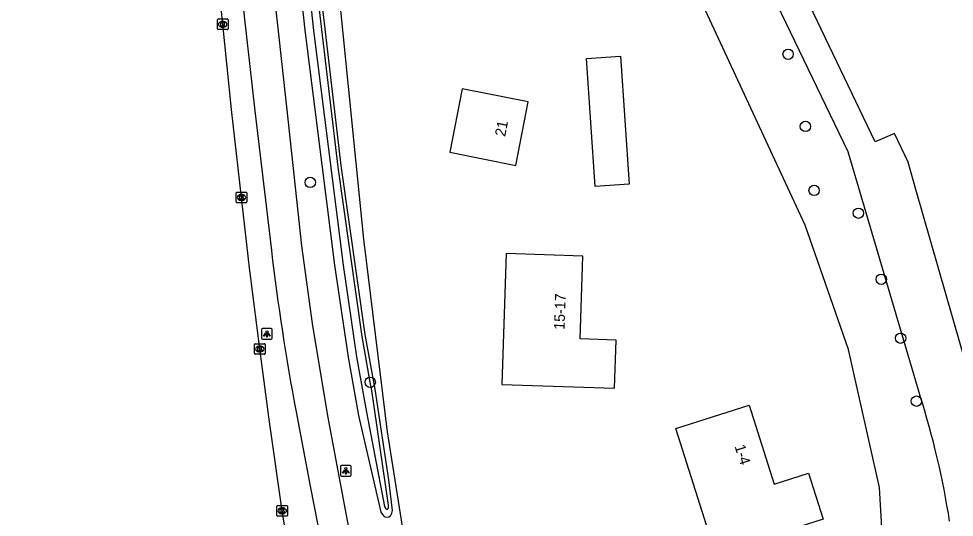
# Model space of a CAD drawing. Extents: x 159451 to 160663, y 388402 to 389723.
# Drawn here: x 159455.9 to 159544.3, y 389152.9 to 389199.9 of the extents above; entities that cross this region are included whole.
import ezdxf

# ---------------------------------------------------------------- set-up
doc = ezdxf.new("R2010")
doc.units = 0
for name, color, linetype in [('IMGEO_Boom', 7, 'Continuous'), ('IMGEO_Bouwland', 7, 'Continuous'), ('IMGEO_Fietspad_gesloten', 7, 'Continuous'), ('IMGEO_Grasland_overig', 7, 'Continuous'), ('IMGEO_Greppel_droge_sloot', 7, 'Continuous'), ('IMGEO_Groenvoorziening', 7, 'Continuous'), ('IMGEO_Kolk', 7, 'Continuous'), ('IMGEO_Lichtpunt', 7, 'Continuous'), ('IMGEO_Pand', 7, 'Continuous'), ('IMGEO_Pand_nummerreeks', 7, 'Continuous'), ('IMGEO_Pand_vergunning_verleend', 7, 'Continuous'), ('IMGEO_Rijbaan_regionaal_gesloten', 7, 'Continuous')]:
    doc.layers.add(name, color=color, linetype=linetype)

msp = doc.modelspace()

# ---------------------------------------------------------------- linework, layer by layer
at = {"layer": 'IMGEO_Boom'}
for centre in [(159528.616, 389196.58), (159530.24, 389189.771), (159483.48, 389184.488), (159531.071, 389183.726), (159535.251, 389181.578), (159537.411, 389175.343), (159539.233, 389169.779), (159489.139, 389165.616), (159540.731, 389163.833)]:
    msp.add_circle(centre, 0.489, dxfattribs=at)
at = {"layer": 'IMGEO_Bouwland'}
for points in [[(159495.943, 389125.547), (159492.959, 389147.253), (159490.78, 389160.929), (159488.551, 389179.124), (159479.211, 389271.897), (159478.228, 389288.738), (159480.836, 389288.81), (159487.441, 389272.575)], [(159539.156, 389122.203), (159538.081, 389141.023), (159537.243, 389155.693), (159534.303, 389168.702), (159530.224, 389180.456), (159487.441, 389272.575)]]:
    msp.add_lwpolyline(points, dxfattribs=at)
at = {"layer": 'IMGEO_Fietspad_gesloten'}
for points in [[(159455.942, 389525.002), (159456.038, 389522.126), (159456.372, 389512.313), (159456.916, 389496.35), (159457.955, 389465.071), (159459.294, 389436.93), (159461.071, 389403.687), (159462.508, 389376.402), (159464.342, 389348.5), (159465.649, 389329.916), (159467.063, 389310.472), (159468.609, 389291.384), (159470.151, 389272.51), (159471.683, 389255.143), (159473.293, 389238.955), (159476.115, 389210.723), (159476.688, 389204.954), (159478.244, 389191.231), (159479.81, 389178.066)], [(159492.482, 389125.078), (159491.057, 389131.504), (159487.963, 389147.366), (159485.138, 389162.462), (159483.697, 389171.161), (159482.691, 389178.486), (159481.255, 389191.613), (159479.595, 389206.774), (159479.167, 389211.269), (159476.315, 389239.166), (159474.73, 389255.582), (159473.199, 389272.868), (159471.882, 389288.893)], [(159482.145, 389162.815), (159483.459, 389155.81), (159485.311, 389146.532), (159487.529, 389135.114), (159489.673, 389123.332)]]:
    msp.add_lwpolyline(points, dxfattribs=at)
msp.add_arc((159698.001, 389203.668), 219.688, 186.6923, 190.71702, dxfattribs=at)
at = {"layer": 'IMGEO_Grasland_overig'}
for points in [[(159552.375, 389144.269), (159550.196, 389160.656), (159546.355, 389164.126), (159540.689, 389183.824), (159539.945, 389186.409), (159538.67, 389189.107), (159536.847, 389188.304), (159486.712, 389292.863)], [(159493.1, 389273.212), (159500, 389258.58), (159504.093, 389250), (159534.245, 389187.399), (159541.062, 389164.374)]]:
    msp.add_lwpolyline(points, dxfattribs=at)
msp.add_arc((159465.827, 389140.335), 78.982, 8.85455, 17.72, dxfattribs=at)
at = {"layer": 'IMGEO_Greppel_droge_sloot'}
msp.add_lwpolyline([(159481.882, 389216.377), (159483.778, 389198.834), (159486.574, 389176.685), (159487.854, 389168.014), (159488.602, 389163.826), (159488.797, 389162.797), (159490.487, 389153.895), (159490.538, 389153.785), (159490.596, 389153.695), (159490.701, 389153.64), (159490.759, 389153.652), (159490.843, 389153.709), (159490.882, 389153.795), (159490.884, 389153.895), (159490.866, 389154.004), (159489.544, 389163.12), (159489.298, 389164.837), (159489.139, 389165.616), (159488.368, 389169.95), (159486.114, 389185.938), (159483.986, 389203.971)], dxfattribs=at)
at = {"layer": 'IMGEO_Groenvoorziening'}
msp.add_lwpolyline([(159474.893, 389291.192), (159478.151, 389250), (159479.346, 389234.239), (159481.073, 389216.395), (159482.97, 389198.843), (159485.767, 389176.684), (159487.05, 389167.999), (159488.037, 389162.469), (159490.153, 389153.348), (159490.295, 389153.124), (159490.458, 389152.949), (159490.624, 389152.875), (159490.9, 389152.917), (159491.057, 389153.021), (159491.194, 389153.27), (159491.245, 389153.512), (159490.896, 389156.395), (159489.602, 389164.953), (159488.663, 389170.113), (159486.412, 389186.084), (159484.285, 389204.106), (159480.958, 389236.812), (159479.998, 389250), (159476.978, 389291.487)], dxfattribs=at)
at = {"layer": 'IMGEO_Kolk'}
for p, q in [((159474.712, 389198.983), (159474.712, 389199.835)), ((159474.787, 389199.909), (159475.639, 389199.909)), ((159475.2, 389199.689), (159475.225, 389199.689)), ((159475.713, 389199.835), (159475.713, 389198.983)), ((159475.639, 389198.909), (159474.787, 389198.909)), ((159475.223, 389199.129), (159475.198, 389199.129)), ((159476.555, 389183.562), (159477.407, 389183.562)), ((159476.48, 389182.636), (159476.48, 389183.488)), ((159476.991, 389182.782), (159476.966, 389182.782)), ((159476.968, 389183.342), (159476.993, 389183.342)), ((159477.481, 389183.488), (159477.481, 389182.636)), ((159477.407, 389182.562), (159476.555, 389182.562)), ((159478.212, 389168.333), (159478.212, 389169.185)), ((159478.287, 389169.259), (159479.139, 389169.259)), ((159478.7, 389169.039), (159478.725, 389169.039)), ((159479.213, 389169.185), (159479.213, 389168.333)), ((159479.139, 389168.259), (159478.287, 389168.259)), ((159478.723, 389168.479), (159478.698, 389168.479)), ((159480.331, 389153.056), (159480.331, 389153.908)), ((159480.406, 389153.982), (159481.258, 389153.982)), ((159480.819, 389153.762), (159480.844, 389153.762)), ((159481.332, 389153.908), (159481.332, 389153.056)), ((159481.258, 389152.982), (159480.406, 389152.982)), ((159480.842, 389153.202), (159480.817, 389153.202))]:
    msp.add_line(p, q, dxfattribs=at)
for points in [[(159474.712, 389198.983), (159474.712, 389199.835)], [(159474.787, 389199.909), (159475.639, 389199.909)], [(159475.033, 389199.609), (159475.156, 389199.609), (159475.156, 389199.458), (159475.286, 389199.609), (159475.45, 389199.609), (159475.304, 389199.458), (159475.457, 389199.209), (159475.305, 389199.209), (159475.22, 389199.373), (159475.156, 389199.306), (159475.156, 389199.209), (159475.033, 389199.209), (159475.033, 389199.609)], [(159475.713, 389199.835), (159475.713, 389198.983)], [(159475.639, 389198.909), (159474.787, 389198.909)], [(159476.555, 389183.562), (159477.407, 389183.562)], [(159476.48, 389182.636), (159476.48, 389183.488)], [(159476.801, 389183.262), (159476.924, 389183.262), (159476.924, 389183.111), (159477.054, 389183.262), (159477.218, 389183.262), (159477.072, 389183.111), (159477.225, 389182.862), (159477.073, 389182.862), (159476.988, 389183.026), (159476.924, 389182.959), (159476.924, 389182.862), (159476.801, 389182.862), (159476.801, 389183.262)], [(159477.481, 389183.488), (159477.481, 389182.636)], [(159477.407, 389182.562), (159476.555, 389182.562)], [(159478.212, 389168.333), (159478.212, 389169.185)], [(159478.287, 389169.259), (159479.139, 389169.259)], [(159478.533, 389168.959), (159478.656, 389168.959), (159478.656, 389168.808), (159478.786, 389168.959), (159478.95, 389168.959), (159478.804, 389168.808), (159478.957, 389168.559), (159478.805, 389168.559), (159478.72, 389168.723), (159478.656, 389168.656), (159478.656, 389168.559), (159478.533, 389168.559), (159478.533, 389168.959)], [(159479.213, 389169.185), (159479.213, 389168.333)], [(159479.139, 389168.259), (159478.287, 389168.259)], [(159480.331, 389153.056), (159480.331, 389153.908)], [(159480.406, 389153.982), (159481.258, 389153.982)], [(159480.652, 389153.682), (159480.775, 389153.682), (159480.775, 389153.531), (159480.905, 389153.682), (159481.069, 389153.682), (159480.923, 389153.531), (159481.076, 389153.282), (159480.924, 389153.282), (159480.839, 389153.446), (159480.775, 389153.379), (159480.775, 389153.282), (159480.652, 389153.282), (159480.652, 389153.682)], [(159481.332, 389153.908), (159481.332, 389153.056)], [(159481.258, 389152.982), (159480.406, 389152.982)]]:
    msp.add_lwpolyline(points, dxfattribs=at)
for centre, start, end in [((159474.789, 389199.833), 91.55205, 178.44795), ((159474.789, 389199.833), 91.55205, 178.44795), ((159475.637, 389199.833), 1.55205, 88.44795), ((159475.637, 389199.833), 1.55205, 88.44795), ((159474.789, 389198.985), 181.55205, 268.44795), ((159474.789, 389198.985), 181.55205, 268.44795), ((159475.637, 389198.985), 271.55205, 358.44795), ((159475.637, 389198.985), 271.55205, 358.44795), ((159476.557, 389183.486), 91.55205, 178.44795), ((159476.557, 389183.486), 91.55205, 178.44795), ((159477.405, 389183.486), 1.55205, 88.44795), ((159477.405, 389183.486), 1.55205, 88.44795), ((159476.557, 389182.638), 181.55205, 268.44795), ((159476.557, 389182.638), 181.55205, 268.44795), ((159477.405, 389182.638), 271.55205, 358.44795), ((159477.405, 389182.638), 271.55205, 358.44795), ((159478.289, 389169.183), 91.55205, 178.44795), ((159478.289, 389169.183), 91.55205, 178.44795), ((159479.137, 389169.183), 1.55205, 88.44795), ((159479.137, 389169.183), 1.55205, 88.44795), ((159478.289, 389168.335), 181.55205, 268.44795), ((159478.289, 389168.335), 181.55205, 268.44795), ((159479.137, 389168.335), 271.55205, 358.44795), ((159479.137, 389168.335), 271.55205, 358.44795), ((159480.408, 389153.906), 91.55205, 178.44795), ((159480.408, 389153.906), 91.55205, 178.44795), ((159481.256, 389153.906), 1.55205, 88.44795), ((159481.256, 389153.906), 1.55205, 88.44795), ((159480.408, 389153.058), 181.55205, 268.44795), ((159480.408, 389153.058), 181.55205, 268.44795), ((159481.256, 389153.058), 271.55205, 358.44795), ((159481.256, 389153.058), 271.55205, 358.44795)]:
    msp.add_arc(centre, 0.0765, start, end, dxfattribs=at)
for centre, major_axis, ratio, start_param, end_param in [((159475.199, 389199.409), (-0.387, 0.002), 0.722429, 4.712389, 7.853982), ((159475.224, 389199.409), (-0.39, 0.002), 0.717154, 1.570796, 4.712389), ((159476.967, 389183.062), (-0.387, 0.002), 0.722429, 4.712389, 7.853982), ((159476.992, 389183.062), (-0.39, 0.002), 0.717154, 1.570796, 4.712389), ((159478.699, 389168.759), (-0.387, 0.002), 0.722429, 4.712389, 7.853982), ((159478.724, 389168.759), (-0.39, 0.002), 0.717154, 1.570796, 4.712389), ((159480.818, 389153.482), (-0.387, 0.002), 0.722429, 4.712389, 7.853982), ((159480.843, 389153.482), (-0.39, 0.002), 0.717154, 1.570796, 4.712389)]:
    msp.add_ellipse(centre, major_axis=major_axis, ratio=ratio, start_param=start_param, end_param=end_param, dxfattribs=at)
at = {"layer": 'IMGEO_Lichtpunt'}
for p, q in [((159478.889, 389170.583), (159478.889, 389169.776)), ((159478.889, 389170.583), (159478.889, 389169.776)), ((159479.791, 389170.678), (159478.983, 389170.678)), ((159479.791, 389170.678), (159478.983, 389170.678)), ((159479.885, 389169.776), (159479.885, 389170.583)), ((159479.885, 389169.776), (159479.885, 389170.583)), ((159478.983, 389169.682), (159479.791, 389169.682)), ((159478.983, 389169.682), (159479.791, 389169.682)), ((159486.341, 389157.663), (159486.341, 389156.856)), ((159486.341, 389157.663), (159486.341, 389156.856)), ((159487.243, 389157.758), (159486.435, 389157.758)), ((159487.243, 389157.758), (159486.435, 389157.758)), ((159487.337, 389156.856), (159487.337, 389157.663)), ((159487.337, 389156.856), (159487.337, 389157.663)), ((159486.435, 389156.762), (159487.243, 389156.762)), ((159486.435, 389156.762), (159487.243, 389156.762))]:
    msp.add_line(p, q, dxfattribs=at)
for points in [[(159479.263, 389170.247), (159479.302, 389170.219), (159479.114, 389169.957), (159479.076, 389169.984), (159479.263, 389170.247)], [(159479.365, 389170.199), (159479.412, 389170.199), (159479.412, 389169.877), (159479.365, 389169.877), (159479.365, 389170.199)], [(159479.475, 389170.219), (159479.513, 389170.246), (159479.7, 389169.984), (159479.661, 389169.956), (159479.475, 389170.219)], [(159486.715, 389157.327), (159486.754, 389157.299), (159486.566, 389157.037), (159486.528, 389157.064), (159486.715, 389157.327)], [(159486.817, 389157.279), (159486.864, 389157.279), (159486.864, 389156.957), (159486.817, 389156.957), (159486.817, 389157.279)], [(159486.927, 389157.299), (159486.965, 389157.326), (159487.152, 389157.064), (159487.113, 389157.036), (159486.927, 389157.299)]]:
    msp.add_lwpolyline(points, dxfattribs=at)
for centre in [(159479.388, 389170.381), (159486.84, 389157.461)]:
    msp.add_circle(centre, 0.0994, dxfattribs=at)
for centre, start, end in [((159478.983, 389170.583), 90, 180), ((159478.983, 389170.583), 90, 180), ((159479.791, 389170.583), 0, 90), ((159479.791, 389170.583), 0, 90), ((159478.983, 389169.776), 180, 270), ((159478.983, 389169.776), 180, 270), ((159479.791, 389169.776), 270, 0), ((159479.791, 389169.776), 270, 360), ((159486.435, 389157.663), 90, 180), ((159486.435, 389157.663), 90, 180), ((159487.243, 389157.663), 0, 90), ((159487.243, 389157.663), 0, 90), ((159486.435, 389156.856), 180, 270), ((159486.435, 389156.856), 180, 270), ((159487.243, 389156.856), 270, 0), ((159487.243, 389156.856), 270, 360)]:
    msp.add_arc(centre, 0.0946, start, end, dxfattribs=at)
at = {"layer": 'IMGEO_Pand'}
for points in [[(159504.064, 389192.091), (159497.826, 389193.308), (159496.658, 389187.324), (159502.892, 389186.087), (159504.064, 389192.091)], [(159512.369, 389169.587), (159508.962, 389169.711), (159509.239, 389177.532), (159501.991, 389177.773), (159501.559, 389165.416), (159512.206, 389165.051), (159512.369, 389169.587)], [(159518.017, 389161.253), (159524.936, 389163.454), (159527.305, 389155.997), (159530.546, 389157.029), (159531.919, 389152.7), (159521.761, 389149.463), (159518.017, 389161.253)]]:
    msp.add_lwpolyline(points, dxfattribs=at)
at = {"layer": 'IMGEO_Pand_vergunning_verleend'}
msp.add_lwpolyline([(159509.568, 389196.173), (159512.785, 389196.387), (159513.592, 389184.311), (159510.374, 389184.096), (159509.568, 389196.173)], dxfattribs=at)
at = {"layer": 'IMGEO_Rijbaan_regionaal_gesloten'}
msp.add_lwpolyline([(159486.085, 389122.792), (159485.702, 389125.061), (159483.264, 389139.262), (159481.503, 389149.299), (159480.832, 389153.482), (159479.637, 389161.877), (159478.713, 389168.759), (159477.869, 389175.45), (159477.784, 389176.125), (159476.981, 389183.062), (159476.055, 389191.357), (159475.213, 389199.409), (159473.713, 389213.767)], dxfattribs=at)

# ---------------------------------------------------------------- texts
at = {"layer": 'IMGEO_Pand_nummerreeks'}
for s, rotation, p in [('21', 78.95358, (159501.884, 389188.752)), ('15-17', 87.97194, (159507.491, 389170.561)), ('1-4', 287.62397, (159523.547, 389159.568))]:
    msp.add_text(s, height=1, rotation=rotation, dxfattribs=at).set_placement(p)

doc.saveas('drawing.dxf')
